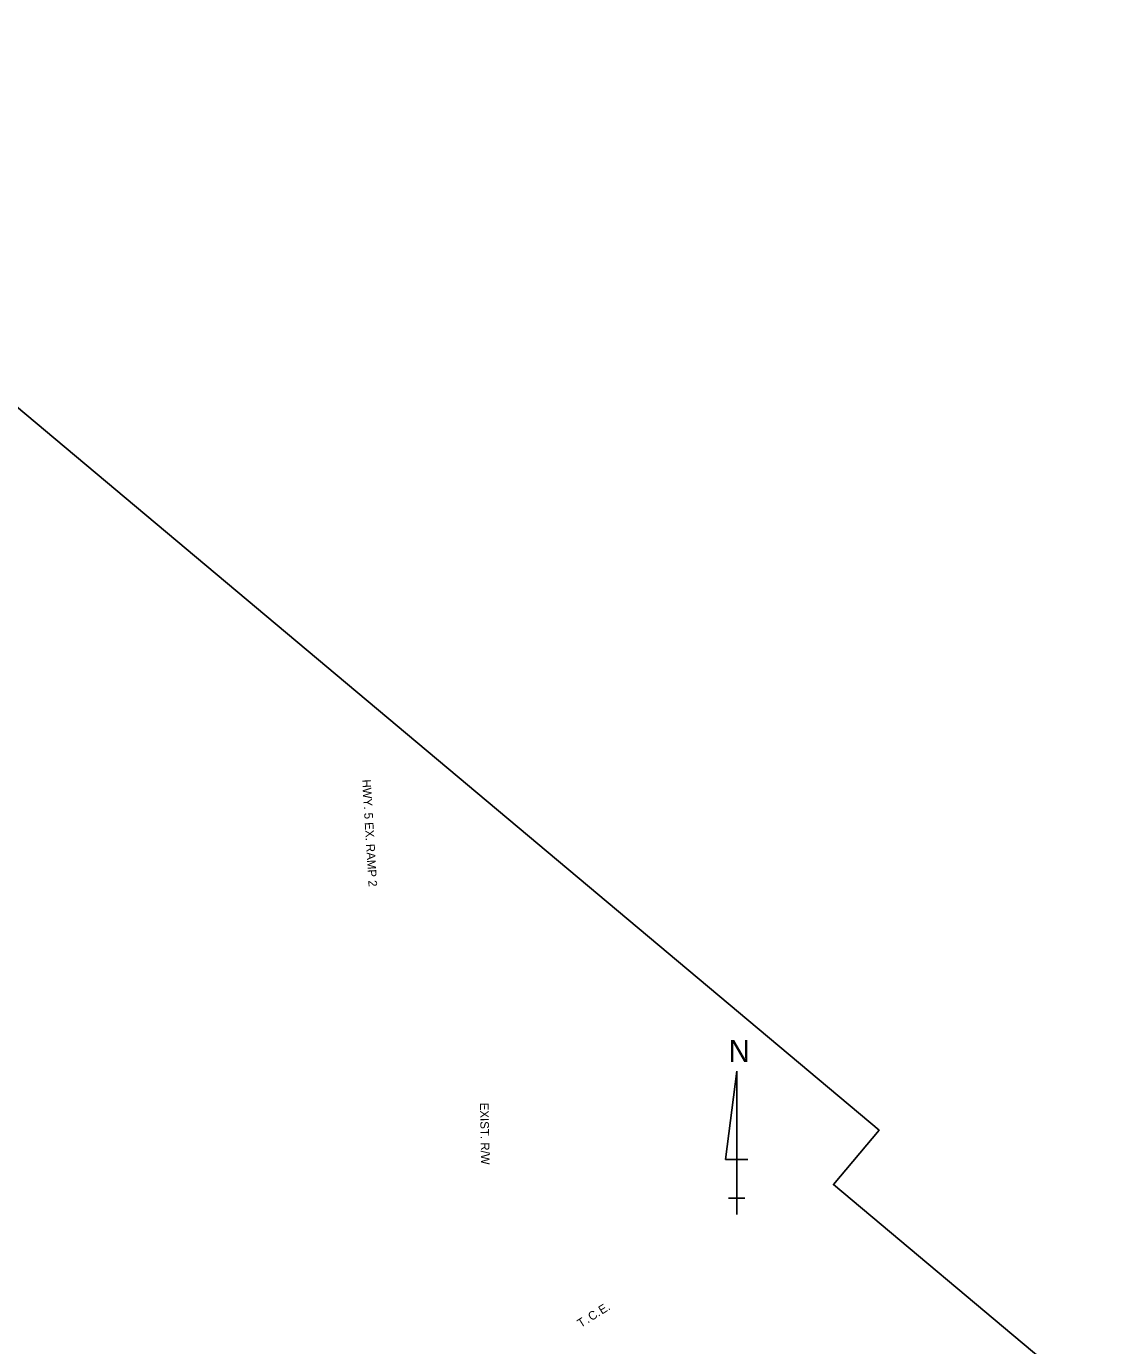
# Model space of a CAD drawing. Extents: x 1292584 to 1294692, y 222754 to 224578.
# Drawn here: x 1293577 to 1294340, y 223658 to 224578 of the extents above; entities that cross this region are included whole.
import ezdxf

# ---------------------------------------------------------------- set-up
doc = ezdxf.new("R2010")
doc.units = 0
for name, color, linetype in [('S_FIBER_OPTIC_CABLE_ANNOT', 7, 'Continuous'), ('S_SHOULDER', 7, 'Continuous'), ('S_STORM_SEWER_ANNOT', 7, 'Continuous'), ('S_SURVEY_TEXT_ANNOT', 7, 'Continuous')]:
    doc.layers.add(name, color=color, linetype=linetype)

msp = doc.modelspace()

# ---------------------------------------------------------------- linework, layer by layer
at = {"layer": 'S_SHOULDER'}
msp.add_lwpolyline([(1292584.05, 223779.83), (1293254.04, 224578.3), (1294171.77, 223808.23), (1294139.92, 223770.28), (1294291.79, 223642.84), (1294281.83, 223630.97), (1294336.68, 223584.95), (1294241.87, 223471.95), (1294339.54, 223390), (1293806.17, 222754.35)], close=True, dxfattribs=at)
msp.add_lwpolyline([(1292584.05, 223779.83), (1293254.04, 224578.3), (1294171.77, 223808.23), (1294139.92, 223770.28), (1294291.79, 223642.84), (1294281.83, 223630.97), (1294336.68, 223584.95), (1294241.87, 223471.95), (1294339.54, 223390), (1293806.17, 222754.35)], close=True, dxfattribs=at)
msp.add_lwpolyline([(1292584.05, 223779.83), (1293254.04, 224578.3), (1294171.77, 223808.23), (1294139.92, 223770.28), (1294291.79, 223642.84), (1294281.83, 223630.97), (1294336.68, 223584.95), (1294241.87, 223471.95), (1294339.54, 223390), (1293806.17, 222754.35)], close=True, dxfattribs=at)
msp.add_lwpolyline([(1292584.05, 223779.83), (1293254.04, 224578.3), (1294171.77, 223808.23), (1294139.92, 223770.28), (1294291.79, 223642.84), (1294281.83, 223630.97), (1294336.68, 223584.95), (1294241.87, 223471.95), (1294339.54, 223390), (1293806.17, 222754.35)], close=True, dxfattribs=at)
msp.add_lwpolyline([(1292584.05, 223779.83), (1293254.04, 224578.3), (1294171.77, 223808.23), (1294139.92, 223770.28), (1294291.79, 223642.84), (1294281.83, 223630.97), (1294336.68, 223584.95), (1294241.87, 223471.95), (1294339.54, 223390), (1293806.17, 222754.35)], close=True, dxfattribs=at)
msp.add_lwpolyline([(1292584.05, 223779.83), (1293254.04, 224578.3), (1294171.77, 223808.23), (1294139.92, 223770.28), (1294291.79, 223642.84), (1294281.83, 223630.97), (1294336.68, 223584.95), (1294241.87, 223471.95), (1294339.54, 223390), (1293806.17, 222754.35)], close=True, dxfattribs=at)
at = {"layer": 'S_SURVEY_TEXT_ANNOT'}
for p, q in [((1294072.48, 223849.34), (1294064.78, 223787.8)), ((1294072.48, 223749.34), (1294072.48, 223849.34)), ((1294072.48, 223849.34), (1294072.48, 223772.42)), ((1294064.78, 223787.8), (1294080.17, 223787.8)), ((1294072.48, 223749.34), (1294072.48, 223772.42)), ((1294072.48, 223760.88), (1294066.71, 223760.88)), ((1294066.71, 223760.88), (1294078.24, 223760.88)), ((1294072.48, 223749.34), (1294072.48, 223760.88))]:
    msp.add_line(p, q, dxfattribs=at)

# ---------------------------------------------------------------- texts
at = {"layer": 'S_FIBER_OPTIC_CABLE_ANNOT'}
msp.add_text('EXIST. R/W', height=6, rotation=271.19347, dxfattribs=at).set_placement((1293893.37, 223827.34))
at = {"layer": 'S_STORM_SEWER_ANNOT'}
for s, rotation, p in [('HWY. 5 EX. RAMP 2', 273.49613, (1293811.24, 224052.73)), ('C', 32.15368, (1293971.15, 223674.92)), ('E', 32.15368, (1293978.43, 223679.5)), ('.', 32.15368, (1293975.95, 223677.94)), ('.', 32.15368, (1293982.99, 223682.36)), ('T', 32.15368, (1293963.71, 223670.24)), ('.', 32.15368, (1293968.67, 223673.36))]:
    msp.add_text(s, height=6, rotation=rotation, dxfattribs=at).set_placement(p)
at = {"layer": 'S_SURVEY_TEXT_ANNOT'}
msp.add_text('N', height=15.38, rotation=360, dxfattribs=at).set_placement((1294066.84, 223855.75))

doc.saveas('drawing.dxf')
